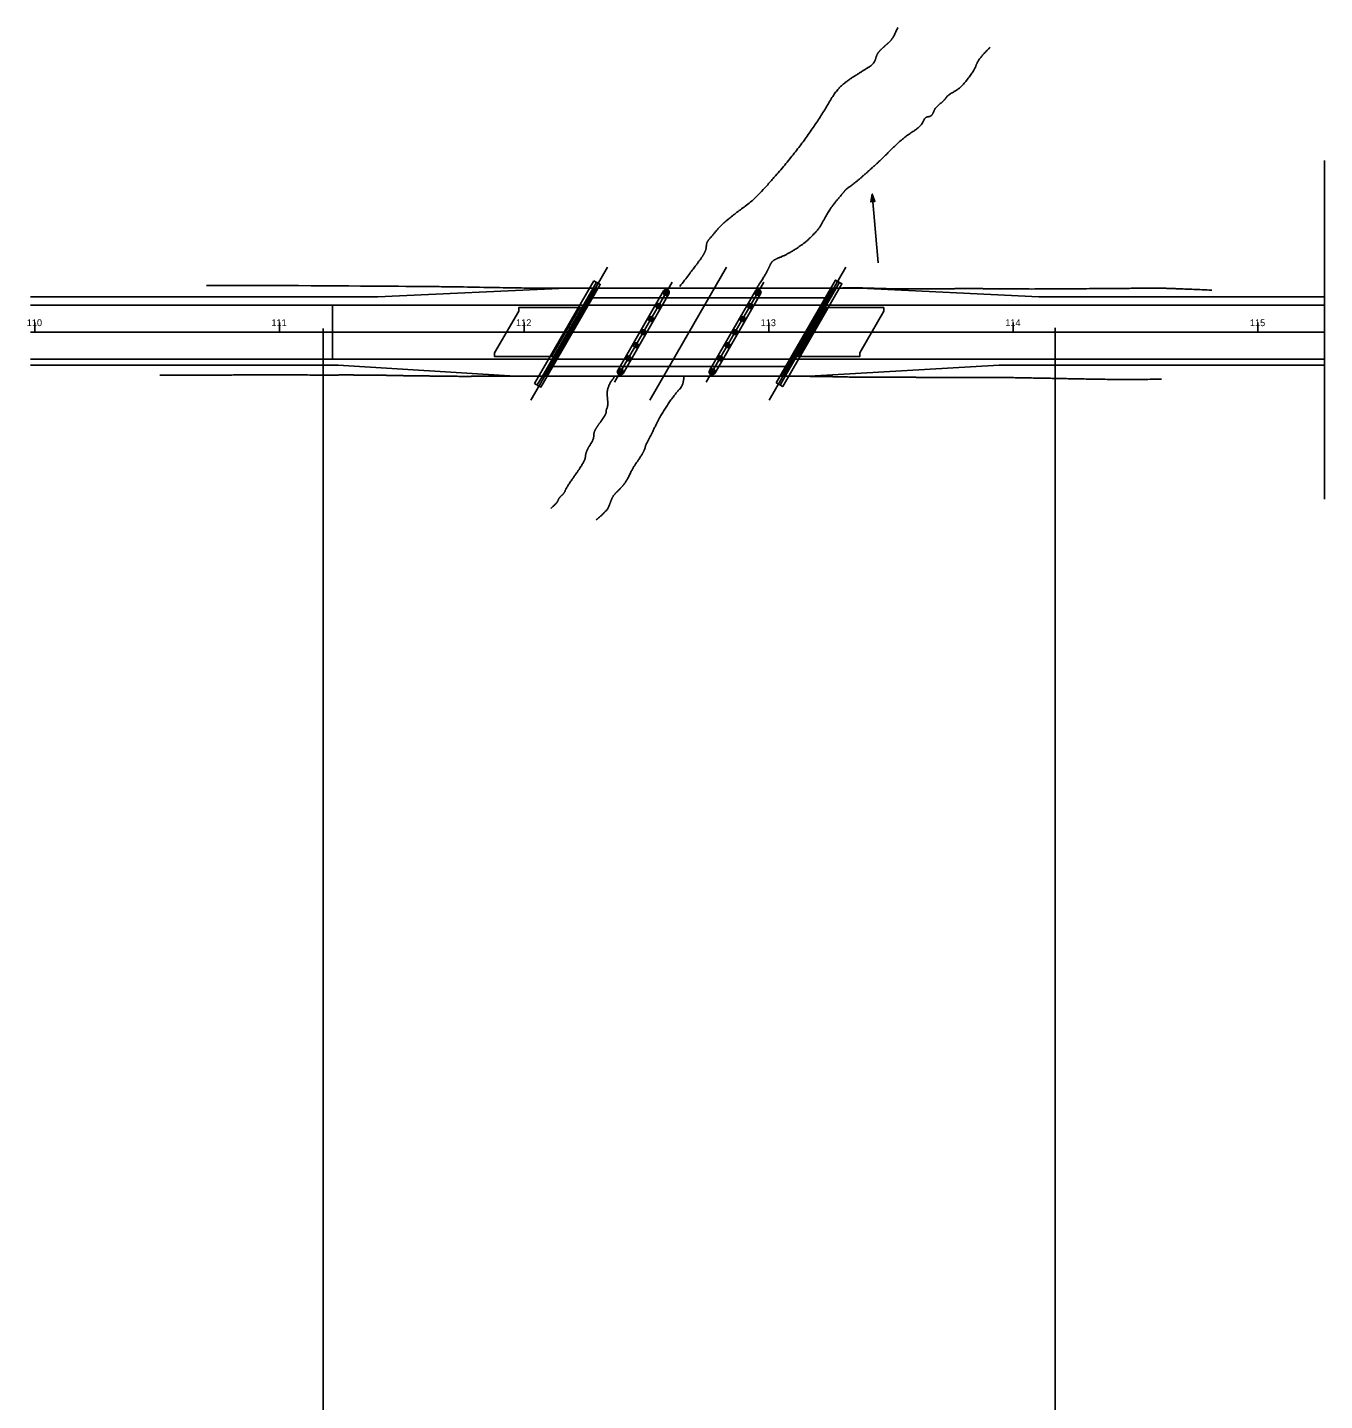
# Model space of a CAD drawing. Extents: x -2063 to 2068, y 79 to 1202.
# Drawn here: x -1872 to -1342, y 640 to 1202 of the extents above; entities that cross this region are included whole.
import ezdxf

# ---------------------------------------------------------------- set-up
doc = ezdxf.new("R2010")
doc.units = 0
for name, color, linetype in [('BR_X_Gen_Approach_Slab', 7, 'Continuous'), ('BR_X_Slab_Centerline', 7, 'Continuous'), ('BR_X_Slab_Const_Joint', 7, 'Continuous'), ('BR_X_Slab_Object', 7, 'Continuous'), ('BR_X_Sub_Centerline', 7, 'Continuous'), ('BR_X_Sub_Deep_Object', 7, 'Continuous'), ('BR_X_Sub_Object', 7, 'Continuous'), ('GE_X_CL_20', 7, 'Continuous'), ('HY_X_Water_Edge', 7, 'Continuous'), ('PM_X_Edge_Line', 7, 'Continuous'), ('PV_X_EOP', 7, 'Continuous'), ('RD_X_GR_Lt', 7, 'Continuous'), ('RD_X_GR_Rt', 7, 'Continuous'), ('SC_Scratch1', 7, 'Continuous'), ('SC_Scratch3', 7, 'Continuous')]:
    doc.layers.add(name, color=color, linetype=linetype)

msp = doc.modelspace()

# ---------------------------------------------------------------- linework, layer by layer
at = {"layer": 'BR_X_Gen_Approach_Slab'}
for points in [[(-1645.67, 1086.97), (-1671.53, 1086.97), (-1671.53, 1085.47), (-1681.35, 1068.47), (-1681.35, 1066.97), (-1657.22, 1066.97)], [(-1546.43, 1086.97), (-1522.29, 1086.97), (-1522.29, 1085.47), (-1532.11, 1068.47), (-1532.11, 1066.97), (-1557.98, 1066.97)]]:
    msp.add_lwpolyline(points, dxfattribs=at)
at = {"layer": 'BR_X_Slab_Centerline'}
msp.add_line((-1586.53, 1103.46), (-1617.87, 1049.18), dxfattribs=at)
at = {"layer": 'BR_X_Slab_Const_Joint'}
for p, q in [((-1643.36, 1090.96), (-1544.12, 1090.96)), ((-1560.29, 1062.96), (-1659.53, 1062.96))]:
    msp.add_line(p, q, dxfattribs=at)
at = {"layer": 'BR_X_Slab_Object'}
msp.add_lwpolyline([(-1641.05, 1094.96), (-1661.84, 1058.96), (-1562.6, 1058.96), (-1541.81, 1094.96)], close=True, dxfattribs=at)
at = {"layer": 'BR_X_Sub_Centerline'}
for p, q in [((-1635.28, 1103.46), (-1666.62, 1049.18)), ((-1569.11, 1049.18), (-1537.78, 1103.46)), ((-1608.78, 1097.39), (-1632.37, 1056.54)), ((-1594.87, 1056.54), (-1571.28, 1097.39))]:
    msp.add_line(p, q, dxfattribs=at)
at = {"layer": 'BR_X_Sub_Deep_Object'}
for centre, radius in [((-1611.33, 1092.99), 1), ((-1611.33, 1092.99), 0.583), ((-1573.83, 1092.99), 1), ((-1573.83, 1092.99), 0.583), ((-1614.41, 1087.65), 1), ((-1614.41, 1087.65), 0.583), ((-1576.91, 1087.65), 1), ((-1576.91, 1087.65), 0.583), ((-1620.58, 1076.96), 1), ((-1617.49, 1082.31), 1), ((-1617.49, 1082.31), 0.583), ((-1583.08, 1076.96), 1), ((-1579.99, 1082.31), 1), ((-1579.99, 1082.31), 0.583), ((-1623.66, 1071.62), 1), ((-1620.58, 1076.96), 0.583), ((-1586.16, 1071.62), 1), ((-1583.08, 1076.96), 0.583), ((-1626.74, 1066.28), 1), ((-1626.74, 1066.28), 0.583), ((-1623.66, 1071.62), 0.583), ((-1589.24, 1066.28), 1), ((-1589.24, 1066.28), 0.583), ((-1586.16, 1071.62), 0.583), ((-1629.83, 1060.94), 1), ((-1629.83, 1060.94), 0.583), ((-1592.33, 1060.94), 1), ((-1592.33, 1060.94), 0.583)]:
    msp.add_circle(centre, radius, dxfattribs=at)
at = {"layer": 'BR_X_Sub_Object'}
for p, q in [((-1639.68, 1097.35), (-1641.05, 1094.96)), ((-1540.44, 1097.34), (-1541.81, 1094.96)), ((-1660.83, 1059.46), (-1640.62, 1094.46)), ((-1631.04, 1061.34), (-1612.28, 1093.84)), ((-1610.11, 1092.59), (-1628.87, 1060.09)), ((-1574.78, 1093.84), (-1593.54, 1061.34)), ((-1591.37, 1060.09), (-1572.61, 1092.59)), ((-1563.03, 1059.46), (-1542.82, 1094.46)), ((-1658.09, 1066.97), (-1646.53, 1086.97)), ((-1545.56, 1086.97), (-1557.11, 1066.97)), ((-1661.84, 1058.96), (-1663.93, 1055.35)), ((-1562.6, 1058.96), (-1564.69, 1055.34))]:
    msp.add_line(p, q, dxfattribs=at)
for points in [[(-1640.76, 1097.97), (-1665.01, 1055.97), (-1662.41, 1054.47), (-1638.16, 1096.47)], [(-1566.21, 1056.22), (-1563.61, 1054.72), (-1539.36, 1096.72), (-1541.96, 1098.22)]]:
    msp.add_lwpolyline(points, close=True, dxfattribs=at)
for points in [[(-1641.34, 1094.46), (-1639.9, 1094.46), (-1660.11, 1059.46), (-1661.55, 1059.46)], [(-1542.1, 1094.46), (-1543.55, 1094.46), (-1563.75, 1059.46), (-1562.31, 1059.46)]]:
    msp.add_lwpolyline(points, dxfattribs=at)
for centre, start, end in [((-1611.2, 1093.21), 330, 150), ((-1573.7, 1093.21), 330, 150), ((-1629.96, 1060.72), 150, 330), ((-1592.46, 1060.72), 150, 330)]:
    msp.add_arc(centre, 1.25, start, end, dxfattribs=at)
at = {"layer": 'GE_X_CL_20'}
for p, q in [((-1869.33, 1076.96), (-1869.33, 1078.96)), ((-1769.33, 1076.96), (-1769.33, 1078.96)), ((-1669.33, 1076.96), (-1669.33, 1078.96)), ((-1569.33, 1076.96), (-1569.33, 1078.96)), ((-1469.33, 1076.96), (-1469.33, 1078.96)), ((-1369.33, 1076.96), (-1369.33, 1078.96)), ((-1871.13, 1076.96), (-1342.11, 1076.96))]:
    msp.add_line(p, q, dxfattribs=at)
at = {"layer": 'HY_X_Water_Edge'}
for points in [[(-1605.69, 1095.59), (-1599.33, 1103.9), (-1596.34, 1107.95), (-1594.81, 1110.91), (-1594.81, 1113.74), (-1591.72, 1117.13), (-1589.21, 1120.36), (-1582.81, 1125.65), (-1575.34, 1130.99), (-1564.09, 1143.56), (-1555.51, 1154.31), (-1548.08, 1165.03), (-1541.66, 1176.03), (-1537.01, 1179.89), (-1531.07, 1183.68), (-1526.03, 1186.76), (-1525.2, 1190.77), (-1521.92, 1193.93), (-1518.46, 1196.87), (-1516.56, 1201.54)], [(-1574.24, 1094.96), (-1571.34, 1099.36), (-1569.23, 1103.32), (-1568.23, 1105.56), (-1566.72, 1106.76), (-1562.9, 1108.24), (-1558.4, 1110.82), (-1553.77, 1114.04), (-1548.4, 1119.64), (-1546.45, 1123.53), (-1543.54, 1128.39), (-1538.85, 1133.99), (-1537.33, 1135.77), (-1534.4, 1137.65), (-1528.52, 1142.79), (-1523, 1147.8), (-1517.01, 1153.94), (-1512.43, 1157.67), (-1507.04, 1161.14), (-1505.32, 1165.06), (-1502.7, 1165.06), (-1501.2, 1168.89), (-1497.9, 1171.32), (-1495.91, 1174.07), (-1490.9, 1176.62), (-1485.01, 1184.38), (-1484.25, 1187.15), (-1481.45, 1190.86), (-1478.78, 1193.43)], [(-1632.13, 1058.96), (-1634.04, 1056.69), (-1635.34, 1053.26), (-1635.34, 1051.06), (-1635.05, 1047.87), (-1635.23, 1046.17), (-1635.74, 1045.29), (-1635.74, 1043.57), (-1638.09, 1040.29), (-1639.93, 1037.61), (-1640.86, 1035.76), (-1640.86, 1033.08), (-1643.23, 1029.55), (-1644.25, 1026.83), (-1644.25, 1025.23), (-1645.88, 1022.25), (-1648.54, 1018.37), (-1652.14, 1013.25), (-1652.92, 1011.01), (-1654.92, 1009.43), (-1655.95, 1006.89), (-1658.35, 1004.91)], [(-1604.03, 1058.83), (-1604.03, 1055.49), (-1607.61, 1051.63), (-1611.25, 1046.41), (-1614.52, 1040.94), (-1618.44, 1032.86), (-1619.57, 1030.96), (-1619.99, 1028.87), (-1622.13, 1025.32), (-1624.86, 1021.47), (-1627.28, 1016.32), (-1629.67, 1013.27), (-1632.84, 1010.34), (-1634.24, 1006.93), (-1635.22, 1004.04), (-1639.81, 1000.23)]]:
    msp.add_open_spline(points, degree=2, dxfattribs=at)
at = {"layer": 'PM_X_Edge_Line'}
for p, q in [((-1871.13, 1087.96), (-1342.11, 1087.96)), ((-1871.13, 1065.96), (-1342.11, 1065.96))]:
    msp.add_line(p, q, dxfattribs=at)
at = {"layer": 'PV_X_EOP'}
for points in [[(-1641.05, 1094.96), (-1652.12, 1094.96), (-1729.14, 1091.46), (-1871.13, 1091.46)], [(-1541.81, 1094.96), (-1531.86, 1094.96), (-1458.88, 1091.46), (-1342.11, 1091.46)], [(-1661.84, 1058.96), (-1672.91, 1058.96), (-1745.31, 1063.46), (-1871.13, 1063.46)], [(-1562.6, 1058.96), (-1552.65, 1058.96), (-1475.05, 1063.46), (-1342.11, 1063.46)]]:
    msp.add_lwpolyline(points, dxfattribs=at)
at = {"layer": 'RD_X_GR_Lt'}
for p, q in [((-1641.05, 1094.96), (-1541.81, 1094.96)), ((-1562.6, 1058.96), (-1661.84, 1058.96))]:
    msp.add_line(p, q, dxfattribs=at)
for points in [[(-1541.81, 1094.96), (-1534.47, 1095.1), (-1527.16, 1094.91), (-1520.81, 1094.7), (-1513.99, 1094.7), (-1506.51, 1094.7), (-1498.2, 1094.7), (-1485.69, 1094.79), (-1468.89, 1094.6), (-1454.41, 1094.6), (-1422.5, 1094.87), (-1409.42, 1094.95), (-1402.74, 1094.75), (-1388.24, 1094.15)], [(-1661.84, 1058.96), (-1674.05, 1058.95), (-1680.68, 1058.96), (-1687.78, 1058.96), (-1692.94, 1058.84), (-1703.25, 1058.99), (-1716.93, 1059.11), (-1728.15, 1059.37), (-1736.51, 1059.37), (-1742.13, 1059.52), (-1748.18, 1059.34), (-1757.36, 1059.45), (-1781.19, 1059.57), (-1793.24, 1059.35), (-1811.4, 1059.28), (-1818.22, 1059.36)]]:
    msp.add_open_spline(points, degree=2, dxfattribs=at)
at = {"layer": 'RD_X_GR_Rt'}
for points, degree in [([(-1641.05, 1094.96), (-1658.64, 1095.02), (-1666.44, 1094.93), (-1674.15, 1095.08), (-1687.48, 1095.31), (-1700.96, 1095.54), (-1709.65, 1095.61), (-1787.31, 1096.21), (-1799.2, 1095.98)], 3), ([(-1562.6, 1058.96), (-1553.73, 1058.96), (-1549.2, 1058.76), (-1546.01, 1058.76), (-1542.03, 1058.76), (-1534.46, 1058.54), (-1526.76, 1058.54), (-1513.85, 1058.54), (-1501.84, 1058.4), (-1498.65, 1058.43), (-1495.04, 1058.43), (-1484.4, 1058.43), (-1478.89, 1058.43), (-1472.68, 1058.43), (-1455.99, 1058.11), (-1440.74, 1057.82), (-1426.13, 1057.56), (-1408.77, 1057.7)], 2)]:
    msp.add_open_spline(points, degree=degree, dxfattribs=at)
at = {"layer": 'SC_Scratch1'}
for p, q in [((-1342.11, 1147.2), (-1342.11, 1008.64)), ((-1747.68, 1076.96), (-1747.68, 1087.96)), ((-1869.33, 1078.96), (-1869.33, 1080.96)), ((-1769.33, 1078.96), (-1769.33, 1080.96)), ((-1669.33, 1078.96), (-1669.33, 1080.96)), ((-1651.09, 1079.09), (-1651.52, 1079.34)), ((-1650.44, 1078.71), (-1651.09, 1079.09)), ((-1650.44, 1078.71), (-1649.9, 1078.4)), ((-1649.9, 1078.4), (-1649.35, 1078.09)), ((-1649.55, 1078.75), (-1649.12, 1078.5)), ((-1569.33, 1078.96), (-1569.33, 1080.96)), ((-1550.12, 1083.08), (-1550.55, 1083.33)), ((-1549.58, 1082.77), (-1550.12, 1083.08)), ((-1549.45, 1083.24), (-1549.88, 1083.49)), ((-1549.04, 1082.46), (-1549.58, 1082.77)), ((-1549.04, 1082.46), (-1548.39, 1082.08)), ((-1548.39, 1082.08), (-1547.95, 1081.83)), ((-1469.33, 1078.96), (-1469.33, 1080.96)), ((-1369.33, 1078.96), (-1369.33, 1080.96)), ((-1747.68, 1065.96), (-1747.68, 1076.96))]:
    msp.add_line(p, q, dxfattribs=at)
msp.add_lwpolyline([(-1527.01, 1133.43), (-1527.59, 1130.29), (-1526.75, 1130.36), (-1525.91, 1130.44), (-1527.01, 1133.39), (-1524.57, 1105.27)], dxfattribs=at)
at = {"layer": 'SC_Scratch3'}
for p, q in [((-1751.45, 298.64), (-1751.45, 1078.48)), ((-1452.21, 298.54), (-1452.21, 1078.77))]:
    msp.add_line(p, q, dxfattribs=at)

# ---------------------------------------------------------------- texts
at = {"layer": 'GE_X_CL_20'}
for s, p in [('110', (-1872.61, 1079.41)), ('111', (-1772.61, 1079.41)), ('112', (-1672.61, 1079.41)), ('113', (-1572.61, 1079.41)), ('114', (-1472.61, 1079.41)), ('115', (-1372.61, 1079.41))]:
    msp.add_text(s, height=2.8, dxfattribs=at).set_placement(p)

doc.saveas('drawing.dxf')
